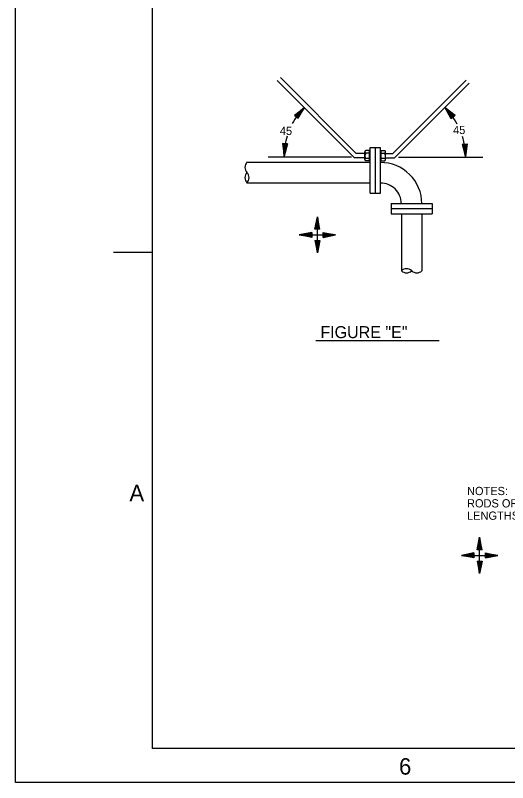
# Model space of a CAD drawing. Extents: x 9999.96 to 10005.26, y 9999.88 to 10002.38.
# Drawn here: x 9999.96 to 10000.559, y 9999.885 to 10000.818 of the extents above; entities that cross this region are included whole.
import ezdxf

# ---------------------------------------------------------------- set-up
doc = ezdxf.new("R2010")
doc.units = 0
doc.layers.add('Level 1', color=7, linetype='Continuous')
doc.layers.add('Level 2', color=7, linetype='Continuous')

msp = doc.modelspace()

# ---------------------------------------------------------------- linework, layer by layer
at = {"layer": 'Level 1'}
for p, q in [((9999.96033, 9999.88453), (9999.96033, 10002.38453)), ((10000.127, 9999.9262), (10000.127, 10002.34286)), ((10000.07949, 10000.53006), (10000.12685, 10000.53006)), ((10003.41867, 9999.9262), (10000.127, 9999.9262)), ((10003.46033, 9999.88453), (9999.96033, 9999.88453))]:
    msp.add_line(p, q, dxfattribs=at)
at = {"layer": 'Level 2'}
for p, q in [((10000.28269, 10000.74225), (10000.37447, 10000.6501)), ((10000.27855, 10000.73892), (10000.37243, 10000.64467)), ((10000.41901, 10000.64994), (10000.50806, 10000.73899)), ((10000.42122, 10000.64466), (10000.51206, 10000.73549)), ((10000.29951, 10000.69668), (10000.3117, 10000.70602)), ((10000.3117, 10000.70602), (10000.30008, 10000.69618)), ((10000.3117, 10000.70602), (10000.30071, 10000.6956)), ((10000.3117, 10000.70602), (10000.30122, 10000.69519)), ((10000.30174, 10000.69472), (10000.3117, 10000.70602)), ((10000.3117, 10000.70602), (10000.30232, 10000.69422)), ((10000.3117, 10000.70602), (10000.30286, 10000.69372)), ((10000.3117, 10000.70602), (10000.30342, 10000.69326)), ((10000.30405, 10000.69272), (10000.3117, 10000.70602)), ((10000.4925, 10000.69416), (10000.48254, 10000.70546)), ((10000.49019, 10000.69216), (10000.48254, 10000.70546)), ((10000.49473, 10000.69611), (10000.48254, 10000.70546)), ((10000.48254, 10000.70546), (10000.49138, 10000.69316)), ((10000.48254, 10000.70546), (10000.49353, 10000.69504)), ((10000.48254, 10000.70546), (10000.49082, 10000.6927)), ((10000.48254, 10000.70546), (10000.49192, 10000.69366)), ((10000.48254, 10000.70546), (10000.49302, 10000.69463)), ((10000.48254, 10000.70546), (10000.49416, 10000.69561)), ((10000.29951, 10000.69668), (10000.30405, 10000.69272)), ((10000.49473, 10000.69611), (10000.49019, 10000.69216)), ((10000.29097, 10000.66165), (10000.28495, 10000.66207)), ((10000.28495, 10000.66207), (10000.28692, 10000.64684)), ((10000.28692, 10000.64684), (10000.28577, 10000.66201)), ((10000.28692, 10000.64684), (10000.28649, 10000.66198)), ((10000.28692, 10000.64684), (10000.28724, 10000.66192)), ((10000.28799, 10000.66186), (10000.28692, 10000.64684)), ((10000.28692, 10000.64684), (10000.2887, 10000.66181)), ((10000.28692, 10000.64684), (10000.28936, 10000.66178)), ((10000.28692, 10000.64684), (10000.2902, 10000.66171)), ((10000.29097, 10000.66165), (10000.28692, 10000.64684)), ((10000.39145, 10000.60181), (10000.39145, 10000.65724)), ((10000.39145, 10000.65724), (10000.40393, 10000.65724)), ((10000.39776, 10000.65724), (10000.39776, 10000.60181)), ((10000.40393, 10000.60181), (10000.40393, 10000.65724)), ((10000.50327, 10000.66108), (10000.50929, 10000.66151)), ((10000.50327, 10000.66108), (10000.50732, 10000.64628)), ((10000.50732, 10000.64628), (10000.50404, 10000.66115)), ((10000.50732, 10000.64628), (10000.50488, 10000.66122)), ((10000.50732, 10000.64628), (10000.50554, 10000.66125)), ((10000.50625, 10000.6613), (10000.50732, 10000.64628)), ((10000.50732, 10000.64628), (10000.507, 10000.66135)), ((10000.50929, 10000.66151), (10000.50732, 10000.64628)), ((10000.50732, 10000.64628), (10000.50847, 10000.66145)), ((10000.50732, 10000.64628), (10000.50775, 10000.66142)), ((10000.38507, 10000.6501), (10000.37447, 10000.6501)), ((10000.38515, 10000.64244), (10000.38514, 10000.65209)), ((10000.39059, 10000.6505), (10000.38611, 10000.6505)), ((10000.39059, 10000.6537), (10000.38615, 10000.6537)), ((10000.39059, 10000.64082), (10000.39059, 10000.6537)), ((10000.40478, 10000.64084), (10000.40478, 10000.65373)), ((10000.40478, 10000.65373), (10000.40924, 10000.65373)), ((10000.40478, 10000.65051), (10000.40927, 10000.65051)), ((10000.41025, 10000.64247), (10000.41025, 10000.65211)), ((10000.41027, 10000.64994), (10000.41901, 10000.64994)), ((10000.24182, 10000.63948), (10000.39145, 10000.63948)), ((10000.36869, 10000.64554), (10000.26766, 10000.64554)), ((10000.38507, 10000.64467), (10000.37243, 10000.64467)), ((10000.39059, 10000.64401), (10000.38611, 10000.64401)), ((10000.39059, 10000.64082), (10000.38611, 10000.64082)), ((10000.40478, 10000.64404), (10000.40927, 10000.64404)), ((10000.40478, 10000.64084), (10000.40927, 10000.64084)), ((10000.41027, 10000.64466), (10000.42122, 10000.64466)), ((10000.42588, 10000.64554), (10000.5284, 10000.64554)), ((10000.24182, 10000.61431), (10000.39145, 10000.61431)), ((10000.39145, 10000.61448), (10000.39145, 10000.61448)), ((10000.39145, 10000.60181), (10000.40393, 10000.60181)), ((10000.41711, 10000.58907), (10000.46701, 10000.58907)), ((10000.41711, 10000.58907), (10000.41711, 10000.57657)), ((10000.41711, 10000.58282), (10000.46701, 10000.58282)), ((10000.46701, 10000.58907), (10000.46701, 10000.57657)), ((10000.32442, 10000.55789), (10000.32744, 10000.57293)), ((10000.32744, 10000.57293), (10000.32523, 10000.55788)), ((10000.32744, 10000.57293), (10000.32596, 10000.55786)), ((10000.32744, 10000.57293), (10000.3267, 10000.55788)), ((10000.32744, 10000.52894), (10000.32744, 10000.57293)), ((10000.32746, 10000.55786), (10000.32744, 10000.57293)), ((10000.33044, 10000.55788), (10000.32744, 10000.57293)), ((10000.32744, 10000.57293), (10000.32883, 10000.55785)), ((10000.32744, 10000.57293), (10000.32816, 10000.55788)), ((10000.32744, 10000.57293), (10000.32968, 10000.55788)), ((10000.41711, 10000.57657), (10000.46701, 10000.57657)), ((10000.42951, 10000.57657), (10000.42951, 10000.50726)), ((10000.45451, 10000.57657), (10000.45451, 10000.50726)), ((10000.3205, 10000.55393), (10000.30545, 10000.55093)), ((10000.30545, 10000.55093), (10000.3205, 10000.55317)), ((10000.3205, 10000.55393), (10000.32049, 10000.54791)), ((10000.33044, 10000.55788), (10000.32442, 10000.55789)), ((10000.33439, 10000.54793), (10000.3344, 10000.55395)), ((10000.34944, 10000.55093), (10000.33439, 10000.55314)), ((10000.3344, 10000.55395), (10000.34944, 10000.55093)), ((10000.30545, 10000.55093), (10000.32052, 10000.55232)), ((10000.30545, 10000.55093), (10000.3205, 10000.55165)), ((10000.32051, 10000.55095), (10000.30545, 10000.55093)), ((10000.30545, 10000.55093), (10000.34944, 10000.55093)), ((10000.32049, 10000.54791), (10000.30545, 10000.55093)), ((10000.30545, 10000.55093), (10000.32051, 10000.54945)), ((10000.30545, 10000.55093), (10000.3205, 10000.54872)), ((10000.30545, 10000.55093), (10000.3205, 10000.55019)), ((10000.32444, 10000.54399), (10000.33046, 10000.54398)), ((10000.32444, 10000.54399), (10000.32744, 10000.52894)), ((10000.32744, 10000.52894), (10000.3252, 10000.54399)), ((10000.32744, 10000.52894), (10000.32604, 10000.54401)), ((10000.32744, 10000.52894), (10000.32672, 10000.54399)), ((10000.32742, 10000.544), (10000.32744, 10000.52894)), ((10000.32744, 10000.52894), (10000.32892, 10000.544)), ((10000.32744, 10000.52894), (10000.32965, 10000.54399)), ((10000.32744, 10000.52894), (10000.32818, 10000.54399)), ((10000.33046, 10000.54398), (10000.32744, 10000.52894)), ((10000.34944, 10000.55093), (10000.33436, 10000.54953)), ((10000.34944, 10000.55093), (10000.33438, 10000.55241)), ((10000.33438, 10000.55091), (10000.34944, 10000.55093)), ((10000.34944, 10000.55093), (10000.33439, 10000.55167)), ((10000.33439, 10000.54793), (10000.34944, 10000.55093)), ((10000.34944, 10000.55093), (10000.33439, 10000.55021)), ((10000.34944, 10000.55093), (10000.33439, 10000.54869)), ((10000.32546, 10000.42226), (10000.47539, 10000.42226)), ((10000.52159, 10000.16795), (10000.52461, 10000.18299)), ((10000.52461, 10000.18299), (10000.52241, 10000.16794)), ((10000.52461, 10000.18299), (10000.52314, 10000.16793)), ((10000.52461, 10000.18299), (10000.52388, 10000.16794)), ((10000.52461, 10000.139), (10000.52461, 10000.18299)), ((10000.52464, 10000.16793), (10000.52461, 10000.18299)), ((10000.52761, 10000.16794), (10000.52461, 10000.18299)), ((10000.52461, 10000.18299), (10000.52601, 10000.16792)), ((10000.52461, 10000.18299), (10000.52533, 10000.16794)), ((10000.52461, 10000.18299), (10000.52685, 10000.16794)), ((10000.51768, 10000.16399), (10000.50263, 10000.16099)), ((10000.50263, 10000.16099), (10000.51768, 10000.16323)), ((10000.50263, 10000.16099), (10000.5177, 10000.16239)), ((10000.50263, 10000.16099), (10000.51768, 10000.16171)), ((10000.51769, 10000.16101), (10000.50263, 10000.16099)), ((10000.50263, 10000.16099), (10000.54661, 10000.16099)), ((10000.51767, 10000.15797), (10000.50263, 10000.16099)), ((10000.50263, 10000.16099), (10000.51769, 10000.15951)), ((10000.50263, 10000.16099), (10000.51768, 10000.15878)), ((10000.50263, 10000.16099), (10000.51768, 10000.16025)), ((10000.51768, 10000.16399), (10000.51767, 10000.15797)), ((10000.52761, 10000.16794), (10000.52159, 10000.16795)), ((10000.54661, 10000.16099), (10000.53154, 10000.15959)), ((10000.54661, 10000.16099), (10000.53155, 10000.16247)), ((10000.53155, 10000.16097), (10000.54661, 10000.16099)), ((10000.53156, 10000.15799), (10000.53157, 10000.16401)), ((10000.54661, 10000.16099), (10000.53156, 10000.1632)), ((10000.54661, 10000.16099), (10000.53156, 10000.16173)), ((10000.53156, 10000.15799), (10000.54661, 10000.16099)), ((10000.54661, 10000.16099), (10000.53156, 10000.16027)), ((10000.54661, 10000.16099), (10000.53156, 10000.15875)), ((10000.53157, 10000.16401), (10000.54661, 10000.16099)), ((10000.52161, 10000.15405), (10000.52764, 10000.15404)), ((10000.52161, 10000.15405), (10000.52461, 10000.139)), ((10000.52461, 10000.139), (10000.52238, 10000.15405)), ((10000.52461, 10000.139), (10000.52322, 10000.15407)), ((10000.52461, 10000.139), (10000.5239, 10000.15405)), ((10000.52459, 10000.15406), (10000.52461, 10000.139)), ((10000.52461, 10000.139), (10000.52609, 10000.15406)), ((10000.52461, 10000.139), (10000.52682, 10000.15405)), ((10000.52461, 10000.139), (10000.52535, 10000.15405)), ((10000.52764, 10000.15404), (10000.52461, 10000.139))]:
    msp.add_line(p, q, dxfattribs=at)
for centre, radius, start, end in [((10000.36997, 10000.64685), 0.08305, 134.56125, 151.61924), ((10000.42427, 10000.64629), 0.08305, 28.38076, 45.43875), ((10000.36997, 10000.64685), 0.08305, 162.97004, 180), ((10000.42427, 10000.64629), 0.08305, 0, 17.02996), ((10000.39109, 10000.64726), 0.00595, 147.00616, 212.94298), ((10000.38695, 10000.65209), 0.0018, 116.78269, 241.8391), ((10000.40843, 10000.65211), 0.0018, 298.1609, 63.21731), ((10000.40429, 10000.64727), 0.00595, 327.05703, 32.99384), ((10000.24829, 10000.63308), 0.009, 135.97881, 224.0225), ((10000.38694, 10000.64242), 0.0018, 117.8877, 242.03419), ((10000.40439, 10000.58892), 0.05, 0.18395, 90.55137), ((10000.40845, 10000.64244), 0.0018, 297.96581, 62.1123), ((10000.24829, 10000.62057), 0.009, 135.9775, 224.02119), ((10000.23535, 10000.62057), 0.009, 315.97881, 44.0225), ((10000.40439, 10000.58892), 0.025, 0.36759, 91.08432), ((10000.43576, 10000.50079), 0.009, 45.9775, 134.02119), ((10000.43576, 10000.51374), 0.009, 225.97881, 314.0225), ((10000.44827, 10000.51374), 0.009, 225.9775, 314.02119)]:
    msp.add_arc(centre, radius, start, end, dxfattribs=at)

# ---------------------------------------------------------------- texts
at = {"layer": 'Level 1'}
for s, p in [('A', (10000.099, 10000.22686)), ('6', (10000.42667, 9999.89428))]:
    msp.add_text(s, height=0.02, dxfattribs=at).set_placement(p)
at = {"layer": 'Level 2'}
for s, height, p in [('45', 0.01, (10000.49234, 10000.67355)), ('45', 0.01, (10000.2818, 10000.67246)), ('FIGURE "E"', 0.014583, (10000.33103, 10000.42529)), ('NOTES:', 0.01, (10000.50931, 10000.23435)), ('RODS OR ANGLES MAY BE USED FOR SUPPORTS INTERCHANGEABLY. SEE MAXIMUM BRACING', 0.01, (10000.50931, 10000.21935)), ('LENGTHS SHOWN IN TABLE 1 AND MINIMUM SIZES AND SPAN INTERVALS IN TABLE 3.', 0.01, (10000.50931, 10000.20435))]:
    msp.add_text(s, height=height, dxfattribs=at).set_placement(p)

doc.saveas('drawing.dxf')
